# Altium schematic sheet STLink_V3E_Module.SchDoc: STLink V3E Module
size A4; Date: Not used; ApprovedBy: Not used; CheckedBy: Not used; Author: Not used; CompanyName: STMicroelectronics; DrawnBy: Not used; Engineer: Not used; Organization: Not used; Address1: Not used; Address2: Not used; Address3: Not used; Address4: Not used; DocumentNumber: Not used; Revision: Not used; SheetNumber: 4; SheetTotal: 7
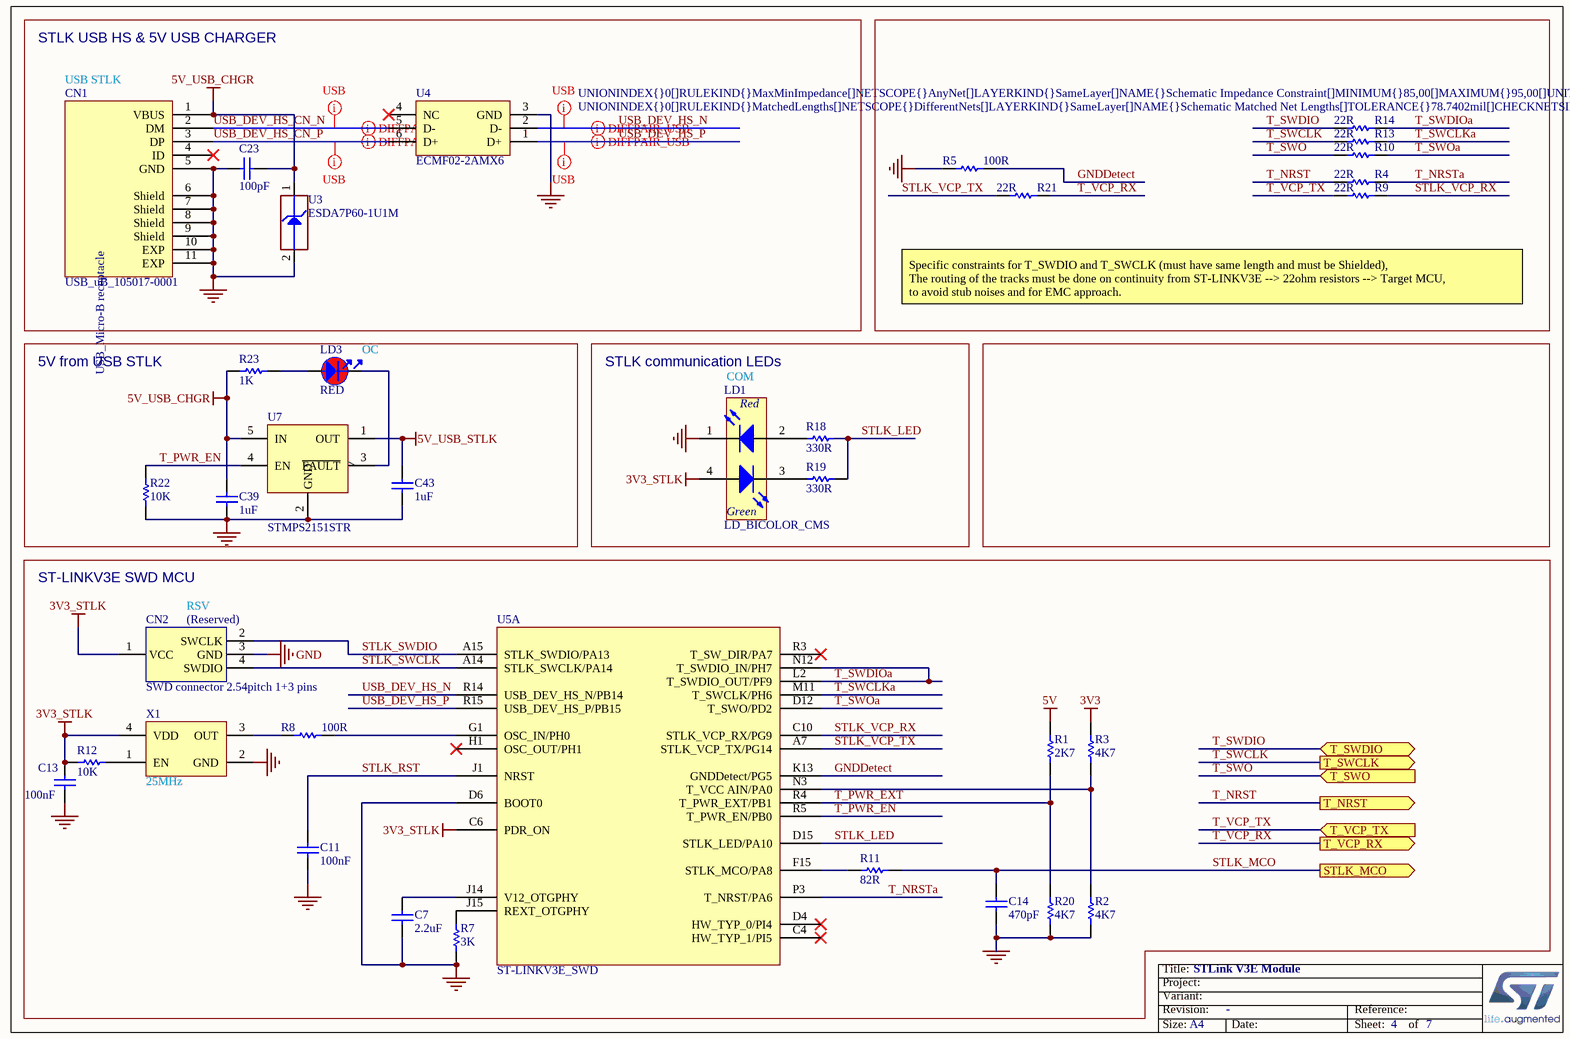
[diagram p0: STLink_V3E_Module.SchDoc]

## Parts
C7  value 2.2uF  [C0603]
C11  value 100nF  [C0402]
C13  value 100nF  [C0402]
C14  value 470pF  [C0402]  (hidden comment: Capacitor)
C23  value 100pF  [C0402]
C39  value 1uF  [C0603]
C43  value 1uF  [C0603]
CN1  value USB_uB_105017-0001  [CON_USBMICROB_MOLEX_105017-0001_H2P90]
CN2  value SWD connector 2.54pitch 1+3 pins  [CON_SAMTEC_TSW-103-07-X-D_CUSTOM_4PINS__V1-3]
LD1  value LD_BICOLOR_CMS  [LED_BI-GR_HSMF-A201-A00J1]
LD3  value RED  [LED_0603_RED_H0P4]
R1  value 2K7  [R0402]
R2  value 4K7  [R0402]
R3  value 4K7  [R0402]
R4  value 22R  [R0402]
R5  value 100R  [R0402]
R7  value 3K  [R0402]
R8  value 100R  [R0402]
R9  value 22R  [R0402]
R10  value 22R  [R0402]
R11  value 82R  [R0402]  (hidden comment: Resistor)
R12  value 10K  [R0402]
R13  value 22R  [R0402]
R14  value 22R  [R0402]
R18  value 330R  [R0603]
R19  value 330R  [R0603]
R20  value 4K7  [R0402]
R21  value 22R  [R0402]
R22  value 10K  [R0402]
R23  value 1K  [R0603]
U3  value ESDA7P60-1U1M  [ESD_QFN2_1P6X1_P125]
U4  value ECMF02-2AMX6  [ESD_QFN-6L_1P7X1P5_P050]
U5  value ST-LINKV3E_SWD  [ICC_UFBGA201_176+25_10X10_P065]  (part A of 2)
U7  value STMPS2151STR  [MOS_SOT23-5L]
X1  value 25MHz  [OSC_NDK_NZ2520SB_4P]

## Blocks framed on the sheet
STLK USB HS & 5V USB CHARGER: C23 CN1 U3 U4
5V from USB STLK: C39 C43 LD3 R22 R23 U7
STLK communication LEDs: LD1 R18 R19
ST-LINKV3E SWD MCU: C7 C11 C13 C14 CN2 R1-R3 R7 R8 R11 R12 R20 U5 X1

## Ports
STLK_MCO, T_NRST, T_SWCLK, T_SWDIO, T_SWO, T_VCP_RX, T_VCP_TX

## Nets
3V3: R3.2
3V3_STLK: C13.2 CN2.1(VCC) LD1.4(YellowGreen_anode) R12.1 U5.C6(PDR_ON) X1.4(VDD)
5V: R1.2
5V_USB_CHGR: C23.2 C39.2 CN1.1(VBUS) R23.1 U3.1(IO1) U7.5(IN)
5V_USB_STLK: C43.2 U7.1(OUT)
GND: C7.1 C11.1 C13.1 C14.1 C23.1 C39.1 C43.1 CN1.5(GND) CN1.6(Shield) CN1.7(Shield) CN1.8(Shield) CN1.9(Shield) CN1.10(EXP) CN1.11(EXP) CN2.3(GND) LD1.1(RED_cathode) R2.1 R5.1 R7.1 R20.1 R22.1 U3.2(GND) U4.3(GND) U5.D6(BOOT0) U7.2(GND) X1.2(GND)
GNDDetect: R5.2 U5.K13(GNDDetect/PG5)
STLK_LED: R18.2 R19.2 U5.D15(STLK_LED/PA10)
STLK_MCO: C14.2 R11.2 ; port STLK_MCO
STLK_RST: C11.2 U5.J1(NRST)
STLK_SWCLK: CN2.4(SWDIO) U5.A14(STLK_SWCLK/PA14)
STLK_SWDIO: CN2.2(SWCLK) U5.A15(STLK_SWDIO/PA13)
STLK_VCP_RX: R9.2 U5.C10(STLK_VCP_RX/PG9)
STLK_VCP_TX: R21.1 U5.A7(STLK_VCP_TX/PG14)
T_NRST: R4.1 ; port T_NRST
T_NRSTa: R4.2 U5.P3(T_NRST/PA6)
T_PWR_EN: R22.2 U5.R5(T_PWR_EN/PB0) U7.4(EN)
T_PWR_EXT: R1.1 R20.2 U5.R4(T_PWR_EXT/PB1)
T_SWCLK: R13.1 ; port T_SWCLK
T_SWCLKa: R13.2 U5.M11(T_SWCLK/PH6)
T_SWDIO: R14.1 ; port T_SWDIO
T_SWDIOa: R14.2 U5.L2(T_SWDIO_OUT/PF9) U5.N12(T_SWDIO_IN/PH7)
T_SWO: R10.1 ; port T_SWO
T_SWOa: R10.2 U5.D12(T_SWO/PD2)
T_VCP_RX: R21.2 ; port T_VCP_RX
T_VCP_TX: R9.1 ; port T_VCP_TX
USB_DEV_HS_CN_N: CN1.2(DM) U4.5(D-)
USB_DEV_HS_CN_P: CN1.3(DP) U4.6(D+)
USB_DEV_HS_N: U4.2(D-) U5.R14(USB_DEV_HS_N/PB14)
USB_DEV_HS_P: U4.1(D+) U5.R15(USB_DEV_HS_P/PB15)
NetC7_2: C7.2 U5.J14(V12_OTGPHY)
NetLD1_2: LD1.2(Red_anode) R18.1
NetLD1_3: LD1.3(YellowGreen_cathode) R19.1
NetLD3_1: LD3.1 R23.2
NetLD3_2: LD3.2 U7.3(~{FAULT})
NetR2_2: R2.2 R3.1 U5.N3(T_VCC_AIN/PA0)
NetR7_2: R7.2 U5.J15(REXT_OTGPHY)
NetR8_1: R8.1 X1.3(OUT)
NetR8_2: R8.2 U5.G1(OSC_IN/PH0)
NetR11_1: R11.1 U5.F15(STLK_MCO/PA8)
NetR12_2: R12.2 X1.1(EN)

Not connected (* = marked no-connect by the designer): CN1 4(ID)*; U4 4(NC)*; U5 C4(HW_TYP_1/PI5)* D4(HW_TYP_0/PI4)* H1(OSC_OUT/PH1)* R3(T_SW_DIR/PA7)*

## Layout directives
differential pair; rule Impedance Constraint [Min = 85.00    Max = 95.00    ]: USB_DEV_HS_CN_N, USB_DEV_HS_CN_P, USB_DEV_HS_N, USB_DEV_HS_P
rule Undefined; rule Matched Net Lengths [Tolerance = 2mm]; rule Impedance Constraint [Min = 85.00    Max = 95.00    ]: USB_DEV_HS_CN_N, USB_DEV_HS_CN_P, USB_DEV_HS_N, USB_DEV_HS_P

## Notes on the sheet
- USB STLK
- Specific constraints for T_SWDIO and T_SWCLK (must have same length and must be Shielded),
  The routing of the tracks must be done on continuity from ST-LINKV3E --> 22ohm resistors --> Target MCU,
  to avoid stub noises and for EMC approach.
- (near LD3) OC
- COM
- (near CN2) (Reserved)
- (near CN2) RSV

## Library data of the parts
C7 = MCD-00012: Capacitor, MLCC, 2.2uF, 10V, X5R, 10%, 0603, T=0,8mm; Manufacturer_Part_Number: CC0603KRX5R6BB225; Manufacturer: YAGEO; Alternate_Manufacturer_Part_Number: C0603C225K8PACTU; Alternate_Manufacturer: KEMET; Provided_By: SUBCO; Initial_Board_Reference: MB1274
C11 C13 = MCD-00102: Capacitor, MLCC, 100nF, 16V, X7R, 10%, 0402, T=0,5mm; Manufacturer_Part_Number: CC0402KRX7R7BB104; Manufacturer: YAGEO; Provided_By: SUBCO; Initial_Board_Reference: MB1262
C14 = MCD-00724: Capacitor, MLCC, 470pF, 50V, NPO, 5%, 0402, T=0,5mm; Manufacturer_Part_Number: CC0402JRNPO9BN471; Manufacturer: YAGEO; Provided_By: SUBCO
C23 = MCD-00205: Capacitor, MLCC, 100pF, 50V, NPO, 5%, 0402, T=0,5mm; Manufacturer_Part_Number: CC0402JRNPO9BN101; Manufacturer: YAGEO; Provided_By: SUBCO; Initial_Board_Reference: MB1361
C39 C43 = MCD-00010: Capacitor, MLCC, 1uF, 16V, X5R, 10%, 0603, T=0,8mm; Manufacturer_Part_Number: CC0603KRX5R7BB105; Manufacturer: YAGEO; Provided_By: SUBCO; Initial_Board_Reference: MB1274
CN1 = MCD-00028: USB-MICRO-B, 0.65mm, RA, SMT, Bottom Mount,; Manufacturer_Part_Number: 1050170001; Manufacturer: MOLEX; Part_Type: Connector; Provided_By: SUBCO; Initial_Board_Reference: MB1274
CN2 = MCD-01430: SWD connector 2.54pitch 1+3 pins - not fitted; Manufacturer_Part_Number: na; Initial_Board_Reference: MB1430
LD1 = MCD-00051: LED Bicolor; Part_Type: Display; Manufacturer_Part_Number: HSMF-A201-A00J1; Manufacturer: AVAGO TECHNOLOGIES; Alternate_Manufacturer_Part_Number: LE-RGW35280; Alternate_Manufacturer: EVERLUCK; Provided_By: SUBCO; Initial_Board_Reference: MB1274
LD3 = MCD-00322: LED, Red, 0603; Part_Type: Display; Manufacturer_Part_Number: 19-217/R6C-AL1M2VY/3T; Manufacturer: EVERLIGHT; Provided_By: SUBCO; Initial_Board_Reference: MB1311
R1 = MCD-00055: Resistor,2K7,0402,1%,1/16W; Manufacturer_Part_Number: RC0402FR-072K7L; Manufacturer: YAGEO; Provided_By: SUBCO; Initial_Board_Reference: MB1274
R2 R3 R20 = MCD-00065: Resistor,4K7,0402,1%,1/16W; Manufacturer_Part_Number: RC0402FR-074K7L; Manufacturer: YAGEO; Alternate_Manufacturer_Part_Number: RT0402FRE074K7L; Provided_By: SUBCO; Initial_Board_Reference: MB1274
R4 R9 R10 R13 R14 R21 = MCD-00189: Resistor,22R,0402,1%,1/16W; Manufacturer_Part_Number: RC0402FR-0722RL; Manufacturer: YAGEO; Provided_By: SUBCO; Initial_Board_Reference: MBxxxx
R5 R8 = MCD-00119: Resistor,100R,0402,1%,1/16W; Manufacturer_Part_Number: RC0402FR-07100RL; Manufacturer: YAGEO; Provided_By: SUBCO; Initial_Board_Reference: MB1262
R7 = MCD-00185: Resistor,3K,0402,1%,1/16W; Manufacturer_Part_Number: RC0402FR-073KL; Manufacturer: YAGEO; Provided_By: SUBCO; Initial_Board_Reference: MBxxxx
R11 = MCD-00525: Resistor,82R,0402,1%,1/16W; Manufacturer_Part_Number: RC0402FR-0782RL; Manufacturer: YAGEO; Provided_By: SUBCO
R12 R22 = MCD-00053: Resistor,10K,0402,1%,1/16W; Manufacturer_Part_Number: RC0402FR-0710KL; Manufacturer: YAGEO; Provided_By: SUBCO; Initial_Board_Reference: MB1274
R18 R19 = MCD-00197: Resistor,330R,0603,1%,1/10W; Manufacturer_Part_Number: RC0603FR-07330RL; Manufacturer: YAGEO; Provided_By: SUBCO; Initial_Board_Reference: MBxxxx
R23 = MCD-00070: Resistor,1K,0603,1%,1/10W; Manufacturer_Part_Number: RC0603FR-071KL; Manufacturer: YAGEO; Provided_By: SUBCO; Initial_Board_Reference: MB1274
U3 = MCD-00251: High power transient voltage suppressor, 7V breakdown; Part_Type: Diode; Manufacturer: STMICROELECTRONICS; BMS_Part_Number: 9179042; Provided_By: SUBCO with ST control; Initial_Board_Reference: MB1311
U4 = MCD-00649: Common mode filter with ESD protection for USB 2.0 interface; Part_Type: Diode; Manufacturer: STMICROELECTRONICS; Provided_By: SUBCO with ST control; Initial_Board_Reference: MB1248
U5 = MCD-00596: STM32F723IEK  (STM32F7) BGA176; Part_Type: IC; Manufacturer_Part_Number: STM32F723IEK6; Manufacturer: STMICROELECTRONICS; BMS_Part_Number: 9175300; Provided_By: SUBCO with ST control; Initial_Board_Reference: MB1331
U7 = MCD-00159: 500mA, Enhanced single channel power switches with active high enable pin; Part_Type: IC; Manufacturer: STMICROELECTRONICS; Alternate_Manufacturer_Part_Number: TPS2051C; Alternate_Manufacturer: TEXAS INSTRUMENTS; BMS_Part_Number: 9159009; Provided_By: SUBCO with ST control; Initial_Board_Reference: MB1264
X1 = MCD-00597: Oscillator 25.00Mhz, -+50PPM, 3.3V, Temp -55 to +125°C; Manufacturer_Part_Number: NZ2520SB 25MHz END4869B; Manufacturer: NDK; Alternate_Manufacturer_Part_Number: KC2520B25.0000C10E00; Alternate_Manufacturer: AVX CORP/KYOCERA CORP; Part_Type: Crystal_Osc; BMS_Part_Number: 9157031; Provided_By: ST; Initial_Board_Reference: MB1331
